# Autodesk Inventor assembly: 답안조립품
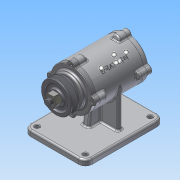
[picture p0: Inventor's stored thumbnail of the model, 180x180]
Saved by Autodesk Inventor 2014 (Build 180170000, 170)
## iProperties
Created: 2015-12
Part Number: 답안조립품
Document SubType Name: Assembly
Designer: Owner
Author: Owner
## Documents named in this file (11)
- C:\Documents and Settings\Owner\바탕 화면\451207V1028\답안조립품.iam
- C:\Documents and Settings\Owner\바탕 화면\451207V1028\본체.ipt
- C:\Documents and Settings\Owner\바탕 화면\451207V1028\베어링 6204.ipt
- C:\Documents and Settings\Owner\바탕 화면\451207V1028\축.ipt
- C:\Documents and Settings\Owner\바탕 화면\451207V1028\커버2.ipt
- C:\Documents and Settings\Owner\바탕 화면\451207V1028\커버.ipt
- C:\Documents and Settings\Owner\바탕 화면\451207V1028\오일실.ipt
- C:\Documents and Settings\Owner\바탕 화면\451207V1028\너트 M12x1.25.ipt
- C:\Documents and Settings\Owner\바탕 화면\451207V1028\V-벨트풀리.ipt
- C:\Documents and Settings\Owner\바탕 화면\451207V1028\키(4 x 4 x 12).ipt
- C:\Documents and Settings\Owner\바탕 화면\451207V1028\볼트 M4 x 12.ipt
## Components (6 placed, 5 different names)
1. KS B 2023 6204 - 20 x 47 x 14:1
2. KS B 2023 6204 - 20 x 47 x 14:2
3. KS B 2804 D D - 20 32 8:1
4. KS B 1012 클래스 1 일반 - 미터 M12x1.25:1 — 각도:3
5. V-벨트풀리:1 — 각도:2
6. KS B 1311 (I) 4 x 4 x 12:1 — 각도:1, 각도:2
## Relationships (3: Angle 3)
- 각도:1 [Angle]: KS B 1311 (I) 4 x 4 x 12:1
- 각도:2 [Angle]: V-벨트풀리:1 ↔ KS B 1311 (I) 4 x 4 x 12:1
- 각도:3 [Angle]: KS B 1012 클래스 1 일반 - 미터 M12x1.25:1
